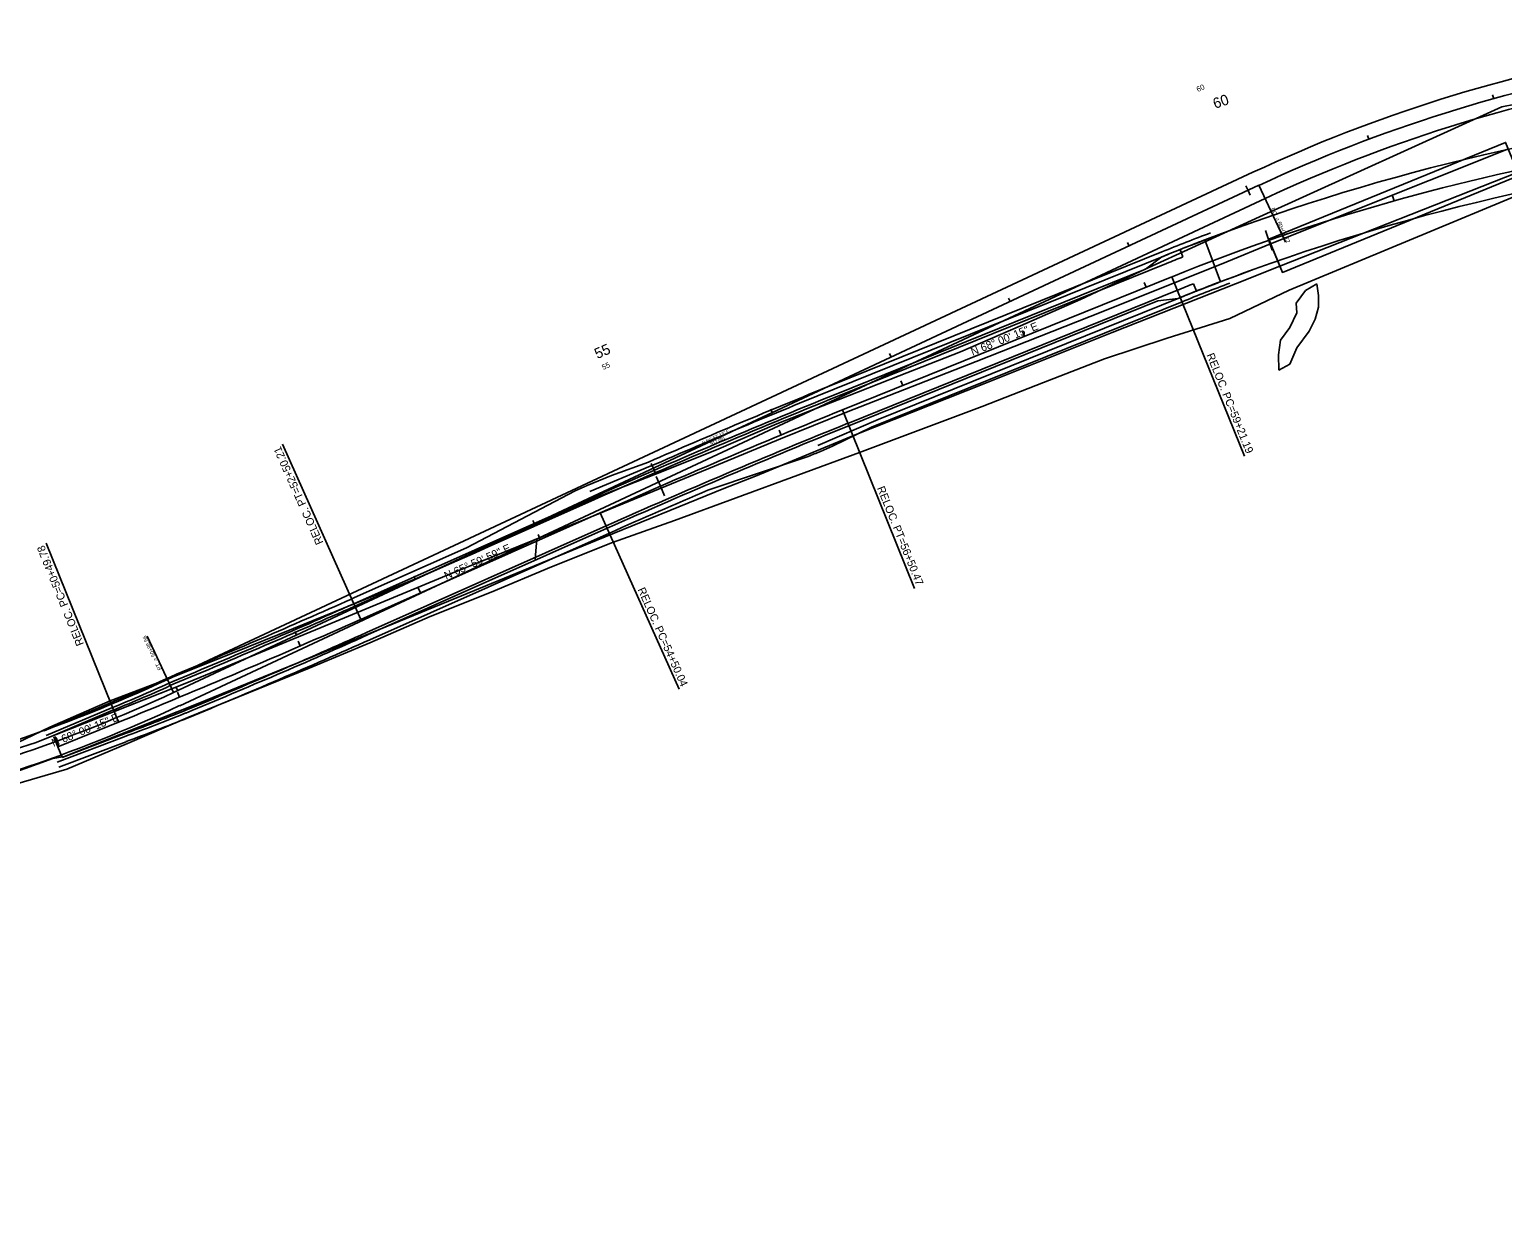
# Model space of a CAD drawing. Extents: x 1965724 to 1970316, y 1117080 to 1118173.
# Drawn here: x 1966749 to 1967871, y 1117080 to 1117994 of the extents above; entities that cross this region are included whole.
import ezdxf

# ---------------------------------------------------------------- set-up
doc = ezdxf.new("R2010")
doc.units = 0
for name, color, linetype in [('Default', 7, 'Continuous'), ('RD_EX_Bridge', 7, 'Continuous'), ('RD_EX_H2O_WetLd', 7, 'Continuous'), ('RD_EX_Road', 7, 'Continuous'), ('RD_EX_RW', 7, 'Continuous'), ('RD_HC_CL', 7, 'Continuous'), ('RD_HC_CL_Rel', 7, 'Continuous'), ('RD_HC_Data', 7, 'Continuous'), ('RD_HC_Data_Rel', 7, 'Continuous'), ('RD_HC_Data_Tic_Rel', 7, 'Continuous'), ('RD_HC_TX_Rel_Sta50', 7, 'Continuous'), ('RD_HC_TX_Sta20', 7, 'Continuous'), ('RD_PD_Bridge', 7, 'Continuous'), ('RD_PD_EarthShd', 7, 'Continuous'), ('RD_PD_Final_TrvlWay', 7, 'Continuous'), ('RD_PD_PaveShd', 7, 'Continuous'), ('RD_Sketch3', 7, 'Continuous'), ('RD_Sketch4', 7, 'Continuous')]:
    doc.layers.add(name, color=color, linetype=linetype)

msp = doc.modelspace()

# ---------------------------------------------------------------- linework, layer by layer
at = {"layer": 'Default'}
msp.add_line((1967135.7, 1117606.5), (1967134.3, 1117591), dxfattribs=at)
at = {"layer": 'RD_EX_Bridge'}
msp.add_lwpolyline([(1967693.2, 1117834.7), (1967873.6, 1117908.4), (1967884, 1117883.1), (1967703.5, 1117809.4), (1967693.2, 1117834.7)], dxfattribs=at)
at = {"layer": 'RD_EX_H2O_WetLd'}
for points in [[(1967700.8, 1117735), (1967700.5, 1117746.7), (1967702.2, 1117757.8), (1967709.3, 1117767.5), (1967714.4, 1117778.7), (1967714, 1117786), (1967721.2, 1117795.5), (1967729.7, 1117800.6)], [(1967700.8, 1117735), (1967700.5, 1117746.7), (1967702.2, 1117757.8), (1967709.3, 1117767.5), (1967714.4, 1117778.7), (1967714, 1117786), (1967721.2, 1117795.5), (1967729.7, 1117800.6)], [(1967700.8, 1117735), (1967709.1, 1117739.5), (1967714.5, 1117752), (1967723.9, 1117764.7), (1967728.5, 1117773.7), (1967731, 1117782.9), (1967731.1, 1117791.9), (1967729.7, 1117800.6)], [(1967700.8, 1117735), (1967709.1, 1117739.5), (1967714.5, 1117752), (1967723.9, 1117764.7), (1967728.5, 1117773.7), (1967731, 1117782.9), (1967731.1, 1117791.9), (1967729.7, 1117800.6)]]:
    msp.add_lwpolyline(points, dxfattribs=at)
at = {"layer": 'RD_EX_Road'}
for p, q in [((1967694.4, 1117831.2), (1967875.7, 1117903.5)), ((1967701.6, 1117814), (1967883.1, 1117885.6))]:
    msp.add_line(p, q, dxfattribs=at)
for points in [[(1966767.3, 1117456.6), (1966870.2, 1117497.3), (1966971.2, 1117539), (1967071.1, 1117580.2), (1967172.6, 1117621.5), (1967270.8, 1117661.7), (1967321.1, 1117682.6), (1967371.5, 1117702.9), (1967470.3, 1117741.6), (1967566.7, 1117779.5), (1967661.2, 1117817.5), (1967694.4, 1117831.2), (1967697.9, 1117822.8)], [(1966769.5, 1117457.5), (1966870.2, 1117497.3), (1966971.2, 1117539), (1967071.1, 1117580.2), (1967172.6, 1117621.5), (1967270.8, 1117661.7), (1967321.1, 1117682.6), (1967371.5, 1117702.9), (1967470.3, 1117741.6), (1967566.7, 1117779.5), (1967661.2, 1117817.5), (1967694.4, 1117831.2)], [(1967302.2, 1117654.1), (1967379.3, 1117686.2), (1967476.1, 1117724.4), (1967573.9, 1117763.5), (1967667.7, 1117800.7), (1967701.6, 1117814), (1967697.9, 1117822.8)], [(1967302.2, 1117654.1), (1967379.3, 1117686.2), (1967476.1, 1117724.4), (1967573.9, 1117763.5), (1967667.7, 1117800.7), (1967701.6, 1117814)], [(1966774.1, 1117439.9), (1966876.2, 1117480.4), (1966978.5, 1117522.1), (1967078.3, 1117563.1), (1967180.7, 1117605.1), (1967278, 1117644.7), (1967302.2, 1117654.1)], [(1966775.8, 1117440.6), (1966876.2, 1117480.4), (1966978.5, 1117522.1), (1967078.3, 1117563.1), (1967180.7, 1117605.1), (1967278, 1117644.7), (1967302.2, 1117654.1)], [(1966736.6, 1117445.6), (1966754.1, 1117451.4), (1966759.7, 1117453.5), (1966769.5, 1117457.5)], [(1965730, 1117080.3), (1965819.8, 1117119.1), (1965907.7, 1117159.3), (1965995.4, 1117199), (1966039.3, 1117218.5), (1966081.2, 1117237.1), (1966124.7, 1117256.6), (1966167.7, 1117275.6), (1966211.5, 1117293.6), (1966257.8, 1117311.6), (1966302.7, 1117327.2), (1966347.9, 1117340), (1966394.8, 1117351.6), (1966441.6, 1117361.9), (1966488.6, 1117372.1), (1966534.9, 1117381.3), (1966581.2, 1117390.9), (1966629.5, 1117400.9), (1966675.6, 1117411.1), (1966721.7, 1117422.8), (1966766.8, 1117439), (1966775.8, 1117440.6)]]:
    msp.add_lwpolyline(points, dxfattribs=at)
at = {"layer": 'RD_EX_RW'}
for points in [[(1967870.6, 1117935.4), (1967922.7, 1117945.6)], [(1966720.5, 1117442), (1966764.7, 1117463), (1966810.5, 1117483.1), (1966857.3, 1117500.8), (1966903.7, 1117519.3), (1966950.1, 1117538.2), (1966996.4, 1117557), (1967042.7, 1117575.8), (1967088.6, 1117595.7), (1967134, 1117616.8), (1967179.6, 1117637.3), (1967226.1, 1117655.7), (1967272.5, 1117674.3), (1967318.5, 1117694.1), (1967365.1, 1117712.2), (1967411.6, 1117730.5), (1967458.2, 1117748.8), (1967504.1, 1117768.7), (1967549.8, 1117788.8), (1967595.2, 1117810), (1967686.2, 1117851.8), (1967870.6, 1117935.4)], [(1967663.6, 1117774.2), (1967708.8, 1117795.8), (1967892.1, 1117872)], [(1966728, 1117416.5), (1966777.6, 1117431), (1966823.7, 1117450.6), (1966869.6, 1117470.3), (1966915.9, 1117489.2), (1966962.2, 1117508), (1967008.4, 1117527.3), (1967054.2, 1117547.3), (1967100.7, 1117565.7), (1967146.8, 1117585), (1967193.3, 1117603.6), (1967240.4, 1117620.4), (1967287.4, 1117637.6), (1967381.3, 1117672.1), (1967428.1, 1117689.7), (1967474.9, 1117707.3), (1967521.5, 1117725.4), (1967568.1, 1117743.6), (1967615.7, 1117759.4), (1967663.6, 1117774.2)]]:
    msp.add_lwpolyline(points, dxfattribs=at)
at = {"layer": 'RD_HC_CL'}
msp.add_line((1966858.9, 1117489.3), (1967685.7, 1117875.7), dxfattribs=at)
for centre, start, end in [((1968170.8, 1116837.5), 84.6661, 115.0463), ((1966373.7, 1118527.5), 281.9047, 295.0463)]:
    msp.add_arc(centre, 1145.9, start, end, dxfattribs=at)
at = {"layer": 'RD_HC_CL_Rel'}
for p, q in [((1967368.4, 1117704.6), (1967619.4, 1117806)), ((1967001.4, 1117545.1), (1967183.9, 1117626.3)), ((1966770.7, 1117448.1), (1966816.9, 1117466.8))]:
    msp.add_line(p, q, dxfattribs=at)
for centre, radius, start, end in [((1968232.6, 1116288.2), 1637, 87.7266, 111.9958), ((1969514.4, 1112392.1), 5729.6, 111.99584, 114.00015), ((1964670.9, 1122779.3), 5729.6, 291.9959, 294.00015)]:
    msp.add_arc(centre, radius, start, end, dxfattribs=at)
at = {"layer": 'RD_HC_Data'}
for p, q in [((1967864.5, 1117941.7), (1967863.7, 1117944.6)), ((1967769.4, 1117910.8), (1967768.3, 1117913.6)), ((1967677.4, 1117871.8), (1967675.7, 1117875.4)), ((1967685.7, 1117875.7), (1967705.9, 1117832.4)), ((1967677.4, 1117871.8), (1967679, 1117868.1)), ((1967586.8, 1117829.4), (1967585.5, 1117832.2)), ((1967496.2, 1117787.1), (1967494.9, 1117789.8)), ((1967405.6, 1117744.8), (1967404.3, 1117747.5)), ((1967315, 1117702.4), (1967313.7, 1117705.1)), ((1967224.4, 1117660.1), (1967222.7, 1117663.7)), ((1967224.4, 1117660.1), (1967226.1, 1117656.5)), ((1967133.8, 1117617.8), (1967132.5, 1117620.5)), ((1967043.2, 1117575.4), (1967041.9, 1117578.1)), ((1966858.9, 1117489.3), (1966838.7, 1117532.4)), ((1966952.6, 1117533.1), (1966951.3, 1117535.8)), ((1966862, 1117490.8), (1966860.7, 1117493.5)), ((1966769.8, 1117452.2), (1966768.4, 1117455.9)), ((1966769.8, 1117452.2), (1966771.2, 1117448.4))]:
    msp.add_line(p, q, dxfattribs=at)
at = {"layer": 'RD_HC_Data_Rel'}
for p, q in [((1967619.4, 1117806), (1967674.6, 1117669.5)), ((1967368.4, 1117704.6), (1967423.4, 1117568.5)), ((1967001.4, 1117545.1), (1966941.9, 1117678.6)), ((1967183.9, 1117626.3), (1967243.9, 1117491.8)), ((1966816.9, 1117466.8), (1966761.8, 1117603.2))]:
    msp.add_line(p, q, dxfattribs=at)
at = {"layer": 'RD_HC_Data_Tic_Rel'}
for p, q in [((1967788.6, 1117863.8), (1967787.5, 1117867.7)), ((1967693.2, 1117833.8), (1967690.6, 1117841.3)), ((1967693.2, 1117833.8), (1967695.8, 1117826.2)), ((1967599.8, 1117798.1), (1967598.3, 1117801.8)), ((1967507.1, 1117760.7), (1967505.6, 1117764.4)), ((1967414.4, 1117723.2), (1967412.9, 1117726.9)), ((1967321.7, 1117685.5), (1967320.2, 1117689.2)), ((1967229.7, 1117646.5), (1967226.5, 1117653.8)), ((1967229.7, 1117646.5), (1967232.9, 1117639.1)), ((1967138.2, 1117606), (1967136.6, 1117609.6)), ((1967046.9, 1117565.3), (1967045.2, 1117569)), ((1966955.4, 1117524.8), (1966953.8, 1117528.5)), ((1966863.4, 1117485.8), (1966861.8, 1117489.5)), ((1966770.7, 1117448.1), (1966767.7, 1117455.5)), ((1966770.7, 1117448.1), (1966773.7, 1117440.7))]:
    msp.add_line(p, q, dxfattribs=at)
at = {"layer": 'RD_PD_Bridge'}
msp.add_line((1967656.5, 1117802.3), (1967644.4, 1117834.1), dxfattribs=at)
for radius in [1654, 1620]:
    msp.add_arc((1968232.6, 1116288.2), radius, 95.4299, 110.8299, dxfattribs=at)
at = {"layer": 'RD_PD_EarthShd'}
for p, q in [((1967360.8, 1117723.7), (1967611.8, 1117825.1)), ((1967390.4, 1117691.4), (1967627.1, 1117787)), ((1967360.7, 1117676.9), (1967390.4, 1117691.4)), ((1967351.6, 1117673), (1967360.7, 1117676.9)), ((1967192.4, 1117654.7), (1967220.6, 1117664.9)), ((1967342.3, 1117669.2), (1967265.9, 1117643.6)), ((1967173.8, 1117647), (1967192.4, 1117654.7)), ((1967164.7, 1117643), (1967082.1, 1117599.6)), ((1967164.7, 1117643), (1967173.8, 1117647)), ((1967008.3, 1117529.5), (1967190.9, 1117610.8)), ((1966994.5, 1117560.6), (1967082.1, 1117599.6)), ((1966760.4, 1117460.2), (1966810.8, 1117481.6)), ((1966771.5, 1117432.5), (1966822.7, 1117451.9))]:
    msp.add_line(p, q, dxfattribs=at)
for centre, radius, start, end in [((1968232.6, 1116288.2), 1657.5, 110.6225, 111.9958), ((1968232.6, 1116288.2), 1620, 110.7424, 111.9958), ((1968232.6, 1116288.2), 1616.5, 110.6173, 111.9958), ((1969514.4, 1112392.1), 5750.1, 111.99584, 113.51008), ((1969514.4, 1112392.1), 5706.6, 112.2722, 112.3722), ((1969514.4, 1112392.1), 5712.6, 113.1791, 114.0002), ((1964670.9, 1122779.3), 5712.6, 292.497, 294.0002), ((1964670.9, 1122779.3), 5746.6, 292.49808, 294.00015), ((1966370.7, 1118566.3), 1170.6, 292.0836, 294.5329), ((1966245.3, 1119024.5), 1675.2, 290.1606, 291.8879)]:
    msp.add_arc(centre, radius, start, end, dxfattribs=at)
at = {"layer": 'RD_PD_Final_TrvlWay'}
for p, q in [((1966854.2, 1117499.3), (1967681, 1117885.6)), ((1966863.5, 1117479.3), (1967690.4, 1117865.7)), ((1967625.6, 1117826.8), (1967627.8, 1117821.2)), ((1967364.3, 1117714.8), (1967615.3, 1117816.2)), ((1967372.6, 1117694.4), (1967623.6, 1117795.8)), ((1967635.8, 1117800.7), (1967638, 1117795.2)), ((1966996.9, 1117555.1), (1967179.5, 1117636.4)), ((1967005.9, 1117535), (1967188.4, 1117616.3)), ((1966767.3, 1117456.6), (1966813.1, 1117476.1)), ((1966774.1, 1117439.9), (1966820.6, 1117457.6))]:
    msp.add_line(p, q, dxfattribs=at)
for centre, radius, start, end in [((1968170.8, 1116837.5), 1156.9, 84.6661, 115.0463), ((1968170.8, 1116837.5), 1134.9, 84.6661, 115.0463), ((1968232.6, 1116288.2), 1654, 110.8299, 111.5299), ((1968232.6, 1116288.2), 1648, 111.5299, 111.9958), ((1968232.6, 1116288.2), 1626, 111.5299, 111.9958), ((1968232.6, 1116288.2), 1620, 110.8299, 111.5299), ((1969514.4, 1112392.1), 5740.6, 111.99584, 114.00015), ((1969514.4, 1112392.1), 5718.6, 111.9958, 114.0002), ((1964670.9, 1122779.3), 5718.6, 292.4981, 294.0002), ((1964670.9, 1122779.3), 5740.6, 292.49808, 294.00015), ((1966373.7, 1118527.5), 1134.9, 281.9047, 295.0463), ((1966370.7, 1118566.3), 1176.6, 292.0861, 294.5277), ((1966373.7, 1118527.5), 1156.9, 281.9047, 295.0463), ((1966245.3, 1119024.5), 1669.2, 290.1606, 291.8879)]:
    msp.add_arc(centre, radius, start, end, dxfattribs=at)
at = {"layer": 'RD_PD_PaveShd'}
for p, q in [((1967599.2, 1117811.9), (1967611.6, 1117821.2)), ((1967363.6, 1117716.7), (1967599.2, 1117811.9)), ((1967373.3, 1117692.6), (1967608.7, 1117787.7)), ((1967608.7, 1117787.7), (1967624.1, 1117789.6)), ((1966996.1, 1117556.9), (1967178.7, 1117638.2)), ((1967006.7, 1117533.2), (1967189.2, 1117614.5)), ((1966761.9, 1117456.5), (1966812.3, 1117477.9)), ((1966770.1, 1117436.3), (1966821.3, 1117455.7))]:
    msp.add_line(p, q, dxfattribs=at)
for centre, radius, start, end in [((1968232.6, 1116288.2), 1654, 110.8299, 112.0495), ((1968232.6, 1116288.2), 1620, 110.8299, 112.0604), ((1969514.4, 1112392.1), 5742.6, 111.99584, 114.00015), ((1969514.4, 1112392.1), 5716.6, 111.9958, 114.0002), ((1964670.9, 1122779.3), 5716.6, 292.4977, 294.0002), ((1964670.9, 1122779.3), 5742.6, 292.49798, 294.00015), ((1966370.7, 1118566.3), 1174.6, 292.0861, 294.5295), ((1966245.3, 1119024.5), 1671.2, 290.1606, 291.8883)]:
    msp.add_arc(centre, radius, start, end, dxfattribs=at)
at = {"layer": 'RD_Sketch3'}
for p, q in [((1967395.6, 1117697.3), (1967625.8, 1117790.3)), ((1967349.7, 1117677.6), (1967395.6, 1117697.3)), ((1967349.7, 1117677.6), (1967349.7, 1117677.6))]:
    msp.add_line(p, q, dxfattribs=at)
msp.add_arc((1968232.6, 1116288.2), 1620, 109.8656, 111.9958, dxfattribs=at)
at = {"layer": 'RD_Sketch4'}
for p, q in [((1967362.1, 1117720.4), (1967613.1, 1117821.8)), ((1967175.9, 1117642.5), (1967222, 1117661.7))]:
    msp.add_line(p, q, dxfattribs=at)
for centre, radius, start, end in [((1968232.6, 1116288.2), 1654, 110.8299, 111.9124), ((1968232.6, 1116288.2), 1654, 111.9124, 111.9958), ((1969514.4, 1112392.1), 5746.6, 111.99584, 113.50999)]:
    msp.add_arc(centre, radius, start, end, dxfattribs=at)

# ---------------------------------------------------------------- texts
at = {"layer": 'RD_HC_Data'}
for s, height, rotation, p in [('PC  = 60+09.22', 3, 295.0463, (1967694.6, 1117857.8)), ('N 64%%d 57\' 13" E', 2.4, 25.0463, (1967262, 1117678.2)), ('912.661', 2.4, 25.0463, (1967268.5, 1117677.5)), ('PT  = 50+96.56', 3, 115.0463, (1966849.9, 1117507.2))]:
    msp.add_text(s, height=height, rotation=rotation, dxfattribs=at).set_placement(p)
at = {"layer": 'RD_HC_Data_Rel'}
for s, rotation, p in [('N 68%%d 00\' 15" E', 21.9958, (1967467.6, 1117745.8)), ('RELOC. PC=59+21.19', 291.9958, (1967645.6, 1117746.5)), ('RELOC. PT=52+50.21', 114.0002, (1966973.1, 1117603.6)), ('RELOC. PT=56+50.47', 291.9958, (1967394.6, 1117645.1)), ('RELOC. PC=50+49.78', 111.9959, (1966790.7, 1117526.3)), ('N 65%%d 59\' 59" E', 24.0002, (1967066.6, 1117575.2)), ('RELOC. PC=54+50.04', 294.0002, (1967212.2, 1117567.8)), ('N 68%%d 00\' 15" E', 21.9959, (1966767.4, 1117447.9))]:
    msp.add_text(s, height=6, rotation=rotation, dxfattribs=at).set_placement(p)
at = {"layer": 'RD_HC_TX_Rel_Sta50'}
for s, rotation, p in [('60', 19.2374, (1967652.3, 1117933.9)), ('55', 23.5006, (1967181.6, 1117743.3))]:
    msp.add_text(s, height=8, rotation=rotation, dxfattribs=at).set_placement(p)
at = {"layer": 'RD_HC_TX_Sta20'}
for s, p in [('60', (1967639.2, 1117946.7)), ('55', (1967186.3, 1117735))]:
    msp.add_text(s, height=4, rotation=25.0463, dxfattribs=at).set_placement(p)

doc.saveas('drawing.dxf')
